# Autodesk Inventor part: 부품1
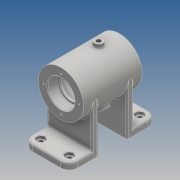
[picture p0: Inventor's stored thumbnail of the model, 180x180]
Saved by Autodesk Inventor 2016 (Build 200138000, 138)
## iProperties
Created: 2017-02
Part Number: 부품1
Material: Generic
Document SubType Name: Modeling
Designer: Administrator
Density: 1 g/cm^3
Appearance: Default
Author: Administrator
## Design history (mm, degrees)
sketch "스케치1"
  geometry: L1 (0, 0)-(54, 0); L2 (54, 104)-(0, 104); L3 (0, 69)-(54, 69); L4 (0, 35)-(54, 35); L5 (0, 104)-(0, 69); L6 (0, 35)-(0, 0); L7 (54, 0)-(54, 35); L8 (54, 69)-(54, 104)
  constraints: 16 end point, 5 parallel, 2 perpendicular, 1 horizontal
  dimensions: "d0" = 54 distance of L2.end L2.start; "d1" = 104 distance of L2.start L1.end; "d4" = 35 distance between parallel lines of L1 L4; "d5" = 54 distance between parallel lines of L6 L7; "d6" = 69 distance between parallel lines of L3 L1; "d7" = 54 distance between parallel lines of L6 L8
extrude "돌출1" new body sketch "스케치1" distance "d8" = 8; taper "d9" = 0 deg
node "작업 평면1"
sketch "스케치2"
  geometry: L1 (8, -69)-(0, -69) reference; L2 (0, -69)-(0, -34) reference; L3 (0, -34)-(8, -34) reference; L4 (8, -34)-(8, -69) reference; L5 (0, 35)-(8, 35) reference; L6 (8, 35)-(8, 0) reference; L7 (8, 0)-(0, 0) reference; L8 (0, 0)-(0, 35) reference; L9 (0, -69)-(0, -34) reference; L10 (60, 18)-(60, -52); L11 (60, -52)-(87, -52); L12 (87, -52)-(87, 18); L13 (87, 18)-(60, 18)
  constraints: 8 end point, 1 horizontal, 1 perpendicular, 1 vertical
  dimensions: "d11" = 70 distance of L10.start L10.end; "d12" = 27 distance of L10.end L11.end; "d13" = 70 distance of L11.end L12.end; "d14" = 60 distance between parallel lines of L8 L10; "d15" = 52 distance between parallel lines of L7 L11
revolve "회전1" sketch "스케치2" stored, may be unused: angle "d16" = 90 deg
sketch "스케치3"
  geometry: L1 (0, 69)-(54, 69) reference; L2 (54, 104)-(54, 69) reference; L3 (54, 69)-(0, 69) reference; L4 (0, 69)-(0, 104) reference; L5 (0, 104)-(54, 104) reference; L6 (0, 0)-(0, 35) reference; L7 (0, 35)-(54, 35) reference; L8 (54, 35)-(54, 0) reference; L9 (54, 0)-(0, 0) reference; L10 (54, 77)-(0, 77); L11 (0, 104)-(0, 69) reference; L12 (0, 35)-(0, 0) reference; L13 (0, 27)-(54, 27); L14 (54, 0)-(54, 35) reference; L15 (54, 27)-(54, 35); L16 (54, 35)-(0, 35) reference; L17 (54, 35)-(0, 35); L18 (0, 35)-(0, 27); L19 (0, 77)-(0, 69); L20 (0, 69)-(54, 69) reference; L21 (0, 69)-(54, 69); L22 (54, 69)-(54, 77)
  constraints: 16 end point, 4 point on line, 3 collinear, 3 perpendicular, 1 horizontal, 1 vertical
  dimensions: "d17" = 8 distance between parallel lines of L1 L10; "d18" = 8 distance between parallel lines of L7 L13
extrude "돌출2" join sketch "스케치3" stored distance "d19" = 8; taper "d20" = 0 deg
node "작업 평면2"
sketch "스케치4"
  geometry: L1 (0, 35)-(8, 35) reference; L2 (8, 35)-(8, 8) reference; L3 (8, 8)-(33, 8) reference; L4 (33, 8)-(33, 18) reference; L5 (33, 18)-(87, 18) reference; L6 (87, 18)-(87, -52) reference; L7 (87, -52)-(33, -52) reference; L8 (33, -52)-(33, -42) reference; L9 (33, -42)-(8, -42) reference; L10 (8, -42)-(8, -69) reference; L11 (8, -69)-(0, -69) reference; L12 (0, -69)-(0, -34) reference; L13 (0, -34)-(33, -34) reference; L14 (33, -34)-(33, 0) reference; L15 (33, 0)-(0, 0) reference; L16 (0, 0)-(0, 35) reference; L17 (60, 18)-(60, -52); L18 (33, -52)-(87, -52) reference; L19 (60, -52)-(76, -52); L20 (76, -52)-(76, -40); L21 (76, -40)-(74, -40); L22 (74, -40)-(74, -37); L23 (74, -37)-(82, -37); L24 (82, -37)-(82, 3); L25 (82, 3)-(74, 3); L26 (74, 3)-(74, 6); L27 (74, 6)-(76, 6); L28 (76, 6)-(76, 18); L29 (76, 18)-(60, 18); L30 (33, 18)-(87, 18) reference
  constraints: 24 end point, 6 perpendicular, 4 point on line, 2 midpoint, 1 collinear, 1 horizontal
  dimensions: "d21" = 16 distance of L17.end L19.end; "d22" = 12 distance of L19.end L20.end; "d23" = 2 distance of L20.end L21.end; "d24" = 3 distance of L21.end L22.end; "d25" = 8 distance of L22.end L23.end; "d26" = 40 distance of L23.end L24.end; "d27" = 8 distance of L24.end L25.end; "d28" = 3 distance of L25.end L26.end; "d29" = 2 distance of L26.end L27.end
revolve "회전2" sketch "스케치4" stored, may be unused: angle "d30" = 90 deg
node "작업 평면3"
sketch "스케치5"
  geometry: L1 (-54, 87)-(0, 87) reference; L2 (-54, 77)-(-54, 104) reference; C1 r 5 at (-27, 62); 1 further point
  constraints: 1 centre point
  dimensions: "d33" = 10 diameter of C1; "d34" = 25 distance from line of L1 C1.centre; "d35" = 27 distance from line of L2 C1.centre
extrude "돌출3" join sketch "스케치5" stored distance "d36" = 8; taper "d37" = 0 deg
sketch "스케치6"
  geometry: C1 r 5 at (0, 0) reference; 1 further point
hole "구멍1" sketch "스케치6" at (0, 0) diameter "d38" = 5.188; stored, may be unused: countersink angle "d42" = 90 deg, drill point angle "d44" = 118 deg; dims "d39" = 12, "d40" = 4, "d41" = 2, "d43" = 15
sketch "스케치7" dims "d45" = 42
  geometry: C1 r 16 at (0, 0) reference; C2 r 27 at (0, 0) reference; 3 further points
  constraints: 2 vertical alignment, 1 coincident, 2 other
hole "구멍2" sketch "스케치7" at (0, -21) diameter "d46" = 3.242; stored, may be unused: countersink angle "d50" = 90 deg, drill point angle "d52" = 118 deg; dims "d47" = 8, "d48" = 4, "d49" = 2, "d51" = 10
sketch "스케치8" dims "d56" = 42
  geometry: C1 r 16 at (0, 0) reference; C2 r 27 at (0, 0) reference; 3 further points
  constraints: 2 vertical alignment, 1 coincident, 2 other
hole "구멍3" sketch "스케치8" at (0, 21) diameter "d57" = 3.242; stored, may be unused: countersink angle "d61" = 90 deg, drill point angle "d63" = 118 deg; dims "d58" = 8, "d59" = 4, "d60" = 2, "d62" = 10
sketch "스케치9" dims "d67" = 9, "d68" = 9, "d69" = 9, "d70" = 9
  geometry: L1 (54, 77)-(54, 104) reference; L2 (54, 104)-(0, 104) reference; L3 (0, 104)-(0, 77) reference; L4 (0, 77)-(54, 77) reference; L5 (54, 104)-(54, 77) reference; L6 (0, 104)-(54, 104) reference; L7 (0, 77)-(0, 104) reference; L8 (0, 69)-(0, 77) reference; L9 (54, 69)-(0, 69) reference; L10 (54, 77)-(54, 69) reference; L11 (54, 27)-(0, 27) reference; L12 (0, 0)-(0, 27) reference; L13 (54, 0)-(0, 0) reference; L14 (54, 27)-(54, 0) reference; L15 (54, 35)-(54, 27) reference; L16 (0, 35)-(54, 35) reference; L17 (0, 27)-(0, 35) reference; L18 (14.5, 91.402)-(10, 88.804); L19 (10, 88.804)-(5.5, 91.402); L20 (5.5, 91.402)-(5.5, 96.598); L21 (5.5, 96.598)-(10, 99.196); L22 (10, 99.196)-(14.5, 96.598); L23 (14.5, 96.598)-(14.5, 91.402); L24 (48.5, 91.402)-(44, 88.804); L25 (44, 88.804)-(39.5, 91.402); L26 (39.5, 91.402)-(39.5, 96.598); L27 (39.5, 96.598)-(44, 99.196); L28 (44, 99.196)-(48.5, 96.598); L29 (48.5, 96.598)-(48.5, 91.402); L30 (14.5, 7.402)-(10, 4.804); L31 (10, 4.804)-(5.5, 7.402); L32 (5.5, 7.402)-(5.5, 12.598); L33 (5.5, 12.598)-(10, 15.196); L34 (10, 15.196)-(14.5, 12.598); L35 (14.5, 12.598)-(14.5, 7.402); L36 (48.5, 7.402)-(44, 4.804); L37 (44, 4.804)-(39.5, 7.402); L38 (39.5, 7.402)-(39.5, 12.598); L39 (39.5, 12.598)-(44, 15.196); L40 (44, 15.196)-(48.5, 12.598); L41 (48.5, 12.598)-(48.5, 7.402); 12 further points
  constraints: 48 end point, 4 coincident, 4 horizontal alignment, 4 midpoint, 2 point on line, 60 other
  dimensions: "d71" = 10 distance from line of L2 point (10, 94); "d72" = 10 distance from line of L2 point (44, 94); "d73" = 10 distance from line of L13 point (10, 10); "d74" = 10 distance from line of L13 point (44, 10); "d75" = 10 distance from line of L3 point (10, 94); "d76" = 10 distance from line of L1 point (44, 94); "d77" = 10 distance from line of L12 point (10, 10); "d78" = 10 distance from line of L14 point (44, 10); "d79" = 60 deg angle of L3 L21; "d80" = 150 deg angle of L2 L28
extrude "돌출4" cut sketch "스케치9" distance "d81" = 3; taper "d82" = 0 deg
sketch "스케치10"
  geometry: L1 (14.5, 12.598)-(14.5, 7.402) reference; L2 (14.5, 12.598)-(10, 15.196) reference; L3 (10, 15.196)-(5.5, 12.598) reference; L4 (5.5, 12.598)-(5.5, 7.402) reference; L5 (5.5, 7.402)-(10, 4.804) reference; L6 (10, 4.804)-(14.5, 7.402) reference; L7 (14.5, 7.402)-(14.5, 12.598) reference; L8 (14.5, 96.598)-(10, 99.196) reference; L9 (10, 99.196)-(5.5, 96.598) reference; L10 (5.5, 96.598)-(5.5, 91.402) reference; L11 (5.5, 91.402)-(10, 88.804) reference; L12 (10, 88.804)-(14.5, 91.402) reference; L13 (14.5, 91.402)-(14.5, 96.598) reference; L14 (48.5, 96.598)-(44, 99.196) reference; L15 (44, 99.196)-(39.5, 96.598) reference; L16 (39.5, 96.598)-(39.5, 91.402) reference; L17 (39.5, 91.402)-(44, 88.804) reference; L18 (44, 88.804)-(48.5, 91.402) reference; L19 (48.5, 91.402)-(48.5, 96.598) reference; L20 (48.5, 12.598)-(44, 15.196) reference; L21 (44, 15.196)-(39.5, 12.598) reference; L22 (39.5, 12.598)-(39.5, 7.402) reference; L23 (39.5, 7.402)-(44, 4.804) reference; L24 (44, 4.804)-(48.5, 7.402) reference; L25 (48.5, 7.402)-(48.5, 12.598) reference; L26 (0, 0)-(0, 35) reference; L27 (0, 35)-(54, 35) reference; L28 (54, 35)-(54, 0) reference; L29 (54, 0)-(0, 0) reference; L30 (54, 104)-(54, 69) reference; L31 (54, 69)-(0, 69) reference; L32 (0, 69)-(0, 104) reference; L33 (0, 104)-(54, 104) reference; C1 r 2.5 at (10, 10); C2 r 2.5 at (44, 10); C3 r 2.5 at (44, 94); C4 r 2.5 at (10, 94)
  constraints: 4 centre point
  dimensions: "d83" = 5 diameter of C1; "d84" = 5 diameter of C2; "d85" = 5 diameter of C3; "d86" = 5 diameter of C4; "d87" = 4.5 distance from line of L13 C4.centre; "d88" = 5.19615 distance of L8.end C4.centre; "d89" = 4.5 distance from line of L1 C1.centre; "d90" = 5.19615 distance of L2.end C1.centre; "d91" = 4.5 distance from line of L25 C2.centre; "d92" = 5.19615 distance of L20.end C2.centre; "d93" = 4.5 distance from line of L19 C3.centre; "d94" = 5.19615 distance of L14.end C3.centre
extrude "돌출5" cut sketch "스케치10" stored distance "d95" = 3; taper "d96" = 0 deg
node "작업 평면4"
sketch "스케치11"
  geometry: L1 (0, 0)-(27, 0); L2 (0, 0)-(27, 0); L3 (0, 0)-(30, 0); L4 (19.37, -18.81)-(21.371, -21.892); L5 (16.339, -25.16)-(21.371, -21.892); L6 (-27, -60)-(-27, 0) reference; L7 (-27, -60)-(27, -60) reference; L8 (16.339, -25.16)-(14.705, -22.644); C1 r 22 at (0, 0) reference; C2 r 22 at (0, 0) reference; C3 r 27 at (0, 0) reference; C4 r 22 at (0, 0) reference; C5 r 27 at (0, 0) reference; A1 r 27 centre (0, 0) between (14.705, -22.644) and (19.37, -18.81); 1 further point
  constraints: 12 end point, 3 horizontal, 2 point on circle, 1 centre point, 1 coincident, 1 horizontal alignment, 1 point on line, 2 other
  dimensions: "d104" = 30 distance from line of C1.centre L5; "d105" = 6 distance from line of point (0, 0) L4; "d107" = 33 deg angle of L7 L5; "d108" = 33 deg angle of L6 L4; "d109" = 57 deg angle of L7 L8; "d110" = 1.63392 horizontal distance of L5.start L8.end
revolve "회전3" sketch "스케치11" stored, may be unused: angle "d111" = 90 deg
sketch "스케치12"
  geometry: C1 r 6 at (0, 0) reference; 1 further point
hole "구멍4" sketch "스케치12" at (0, 0) diameter "d112" = 5.188; stored, may be unused: countersink angle "d116" = 90 deg, drill point angle "d118" = 118 deg; dims "d113" = 16, "d114" = 4, "d115" = 2, "d117" = 20
fillet "모깎기1" dims "d119" = 2
fillet "모깎기2" dims "d120" = 10
fillet "모깎기3" dims "d121" = 2
fillet "모깎기4" dims "d122" = 2
fillet "모깎기5" dims "d123" = 2
fillet "모깎기6" dims "d124" = 0.3
fillet "모깎기7" dims "d125" = 3
chamfer "모따기1" distance "d126" = 1; stored, may be unused: second distance "d127" = 2, angle "d128" = 45 deg
sketch "스케치13"
  geometry: L1 (-27, 16)-(-27, -54) reference; L2 (27, 16)-(27, -54) reference; L3 (-27, -54)-(27, -54) reference; L4 (-27, 16)-(27, 16) reference; L5 (2.402, -2.408)-(2.402, -35.592); L6 (2.402, -35.592)-(-2.402, -35.592); L7 (-2.402, -35.592)-(-2.402, -2.408); L8 (-2.402, -2.408)-(2.402, -2.408); 1 further point
  constraints: 2 other
feature "엠보싱1" sketch "스케치13" dims "d0" = 54, "d1" = 104, "d4" = 35, "d5" = 54, "d6" = 69, "d7" = 54, "d130" = 0.5, "d131" = 0
fillet "모깎기8" dims "d132" = 2
node "솔리드1"
pattern_circular "원형 패턴1" dims angle "d54" = 360 deg
pattern_circular "원형 패턴2" dims angle "d65" = 360 deg
node "절단 모서리 투영1"
node "절단 모서리 투영2"
node "절단 모서리 투영3"
node "절단 모서리 투영4"
node "절단 모서리 투영5"
node "절단 모서리 투영6"
node "절단 모서리 투영7"
node "절단 모서리 투영8"
other parameters: "d31" = -92, "d100" = 57 deg
